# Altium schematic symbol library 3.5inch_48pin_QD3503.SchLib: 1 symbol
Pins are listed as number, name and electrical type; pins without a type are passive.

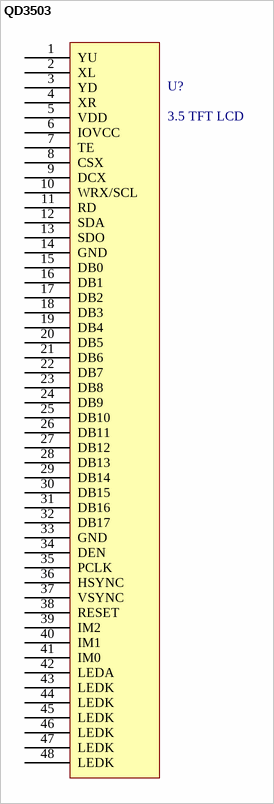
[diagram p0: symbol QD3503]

## QD3503
designator U?, comment 3.5 TFT LCD
3.5 inch TFT LCD
pins: 1 YU, 2 XL, 3 YD, 4 XR, 5 VDD, 6 IOVCC, 7 TE, 8 CSX, 9 DCX, 10 WRX/SCL, 11 RD, 12 SDA, 13 SDO, 14 GND, 15 DB0, 16 DB1, 17 DB2, 18 DB3, 19 DB4, 20 DB5, 21 DB6, 22 DB7, 23 DB8, 24 DB9, 25 DB10, 26 DB11, 27 DB12, 28 DB13, 29 DB14, 30 DB15, 31 DB16, 32 DB17, 33 GND, 34 DEN, 35 PCLK, 36 HSYNC, 37 VSYNC, 38 RESET, 39 IM2, 40 IM1, 41 IM0, 42 LEDA, 43 LEDK, 44 LEDK, 45 LEDK, 46 LEDK, 47 LEDK, 48 LEDK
